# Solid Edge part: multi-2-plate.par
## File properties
Author: Deepak Maini
Template: normal.par
Last saved by: CADCIM
Revision: 6
Application: Solid Edge
Accuracy: 0.99
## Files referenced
..\multi-cutout.asm
ED:\sld-edg-15\cd-models\c09-sld-edg-15\figure28-8&29\multi-cutout.asm
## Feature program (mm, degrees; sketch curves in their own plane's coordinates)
sketch for "unnamed Protrusion 1" plane through (0, 0, 0) normal (0, 0, 1) x-axis (1, 0, 0)
  line (-46.224, -15.84) -> (-46.224, 16.704)
  line (-46.224, 16.704) -> (47.664, 16.704)
  line (47.664, 16.704) -> (47.664, -15.84)
  line (47.664, -15.84) -> (-46.224, -15.84)
extrude "unnamed Protrusion 1" add finite 10.6 along +normal
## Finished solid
Body 1: solid body, 6 faces, 12 edges, 8 vertices.
  Faces by surface: plane 6
  Edges by curve: line 12
Bounding box of the edges (mm): 93.888 x 32.544 x 10.600, from (-46.224, -15.84, 0) to (47.664, 16.704, 10.6).
Planar faces by outward normal: +x 1, +y 1, +z 1, -x 1, -y 1, -z 1
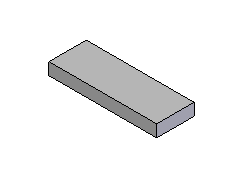
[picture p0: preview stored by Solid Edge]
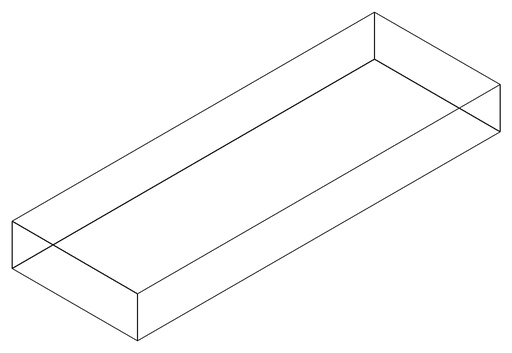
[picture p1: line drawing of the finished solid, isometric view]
